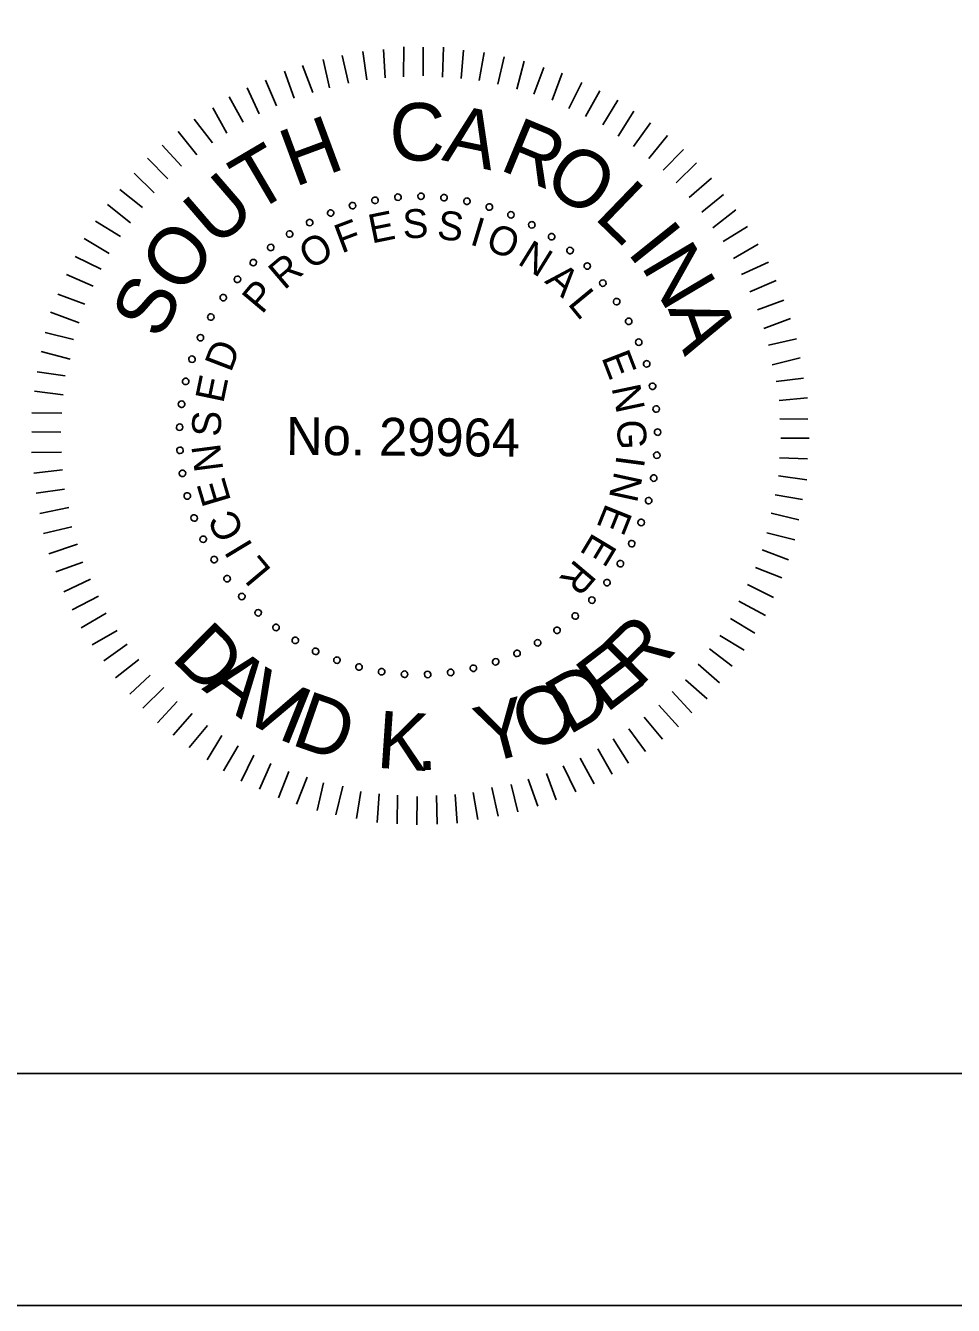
# Model space of a CAD drawing. Extents: x -133.1 to -97, y -1.7 to 20.3.
# Drawn here: x -109.682 to -107.68, y -1.691 to 1.069 of the extents above; entities that cross this region are included whole.
import ezdxf

# ---------------------------------------------------------------- set-up
doc = ezdxf.new("R2010")
doc.units = 0
for name, color, linetype in [('BR_BORDER LINES', 7, 'Continuous'), ('BR_TEXT', 7, 'Continuous'), ('Level 31', 7, 'Continuous')]:
    doc.layers.add(name, color=color, linetype=linetype)

msp = doc.modelspace()

# ---------------------------------------------------------------- linework, layer by layer
at = {"layer": 'BR_BORDER LINES'}
msp.add_line((-131.3076, -1.191), (-97.6416, -1.191), dxfattribs=at)
at = {"layer": 'BR_TEXT'}
for p, q in [((-108.8664, 0.9584), (-108.8658, 1.0227)), ((-108.8243, 0.9606), (-108.8238, 1.0224)), ((-108.7823, 0.9577), (-108.78, 1.022)), ((-109.0262, 0.9348), (-109.0394, 0.9958)), ((-108.9849, 0.9447), (-108.999, 1.0041)), ((-108.9454, 0.9521), (-108.9543, 1.0131)), ((-108.9059, 0.9561), (-108.9097, 1.017)), ((-108.742, 0.9548), (-108.7372, 1.0156)), ((-108.7034, 0.9501), (-108.6926, 1.011)), ((-108.6631, 0.9421), (-108.6489, 1.0012)), ((-109.1019, 0.9122), (-109.1229, 0.9708)), ((-109.0623, 0.9248), (-109.0842, 0.9824)), ((-108.622, 0.9314), (-108.606, 0.9922)), ((-108.5852, 0.9208), (-108.5633, 0.9781)), ((-109.1406, 0.8954), (-109.1642, 0.9514)), ((-108.5458, 0.9076), (-108.5239, 0.9658)), ((-108.5099, 0.8902), (-108.482, 0.9457)), ((-109.2122, 0.8608), (-109.2426, 0.9151)), ((-109.1777, 0.8785), (-109.2039, 0.9345)), ((-108.474, 0.8727), (-108.4427, 0.9282)), ((-109.2475, 0.8371), (-109.278, 0.8914)), ((-108.4364, 0.8544), (-108.4042, 0.9082)), ((-108.4031, 0.8301), (-108.3692, 0.8839)), ((-109.2786, 0.8159), (-109.3177, 0.8668)), ((-108.3699, 0.8083), (-108.3334, 0.8587)), ((-109.3123, 0.7904), (-109.3522, 0.8405)), ((-108.3375, 0.7824), (-108.2968, 0.8318)), ((-109.3451, 0.7658), (-109.3868, 0.8107)), ((-108.3059, 0.7572), (-108.2627, 0.8014)), ((-109.3745, 0.7386), (-109.4188, 0.7827)), ((-108.2779, 0.7295), (-108.2346, 0.7729)), ((-109.4039, 0.7079), (-109.4474, 0.7503)), ((-108.2498, 0.6984), (-108.2022, 0.74)), ((-109.4291, 0.6763), (-109.4786, 0.7154)), ((-108.2226, 0.6664), (-108.1759, 0.7046)), ((-109.4551, 0.6431), (-109.5046, 0.683)), ((-108.1988, 0.6327), (-108.1496, 0.6718)), ((-109.4768, 0.6141), (-109.5306, 0.6472)), ((-108.1768, 0.6034), (-108.1242, 0.6355)), ((-109.5012, 0.5774), (-109.5549, 0.6096)), ((-108.1548, 0.5663), (-108.1013, 0.5976)), ((-109.5186, 0.5432), (-109.575, 0.5711)), ((-108.137, 0.5318), (-108.0793, 0.5588)), ((-109.5361, 0.5065), (-109.5933, 0.5318)), ((-108.1193, 0.4948), (-108.0624, 0.5192)), ((-109.5536, 0.468), (-109.6117, 0.4899)), ((-108.1025, 0.456), (-108.0456, 0.477)), ((-109.5659, 0.4278), (-109.6275, 0.4506)), ((-108.0891, 0.4156), (-108.0314, 0.4374)), ((-109.5782, 0.3918), (-109.639, 0.4069)), ((-108.079, 0.3794), (-108.0189, 0.3935)), ((-109.5854, 0.3498), (-109.6479, 0.3658)), ((-108.0708, 0.3373), (-108.0106, 0.3522)), ((-109.596, 0.3138), (-109.6569, 0.3221)), ((-108.0625, 0.3012), (-108.0033, 0.3084)), ((-109.6006, 0.2727), (-109.6624, 0.2801)), ((-108.056, 0.26), (-107.995, 0.2663)), ((-109.6035, 0.2333), (-109.6679, 0.2338)), ((-108.0546, 0.2205), (-107.9945, 0.22)), ((-109.6056, 0.1921), (-109.6682, 0.1926)), ((-108.0524, 0.1793), (-107.9915, 0.1788)), ((-109.6042, 0.1492), (-109.6686, 0.148)), ((-109.602, 0.1105), (-109.6638, 0.1033)), ((-108.0553, 0.1364), (-107.9952, 0.1342)), ((-108.0574, 0.0978), (-107.9965, 0.0896)), ((-109.598, 0.0693), (-109.659, 0.0604)), ((-108.0645, 0.0566), (-108.0054, 0.0467)), ((-109.5881, 0.0297), (-109.6508, 0.0165)), ((-108.0735, 0.0172), (-108.0135, 0.003)), ((-109.5815, -0.0124), (-109.6426, -0.0265)), ((-108.0824, -0.0248), (-108.0224, -0.0398)), ((-109.5698, -0.0493), (-109.6318, -0.0703)), ((-108.093, -0.0615), (-108.0357, -0.0835)), ((-109.5582, -0.0881), (-109.6167, -0.1091)), ((-108.107, -0.1001), (-108.0506, -0.122)), ((-109.5413, -0.1251), (-109.599, -0.1521)), ((-108.1245, -0.1368), (-108.0681, -0.1647)), ((-109.5244, -0.1613), (-109.5813, -0.1909)), ((-108.1428, -0.1727), (-108.0856, -0.2032)), ((-109.5076, -0.1984), (-109.5619, -0.2297)), ((-108.1612, -0.2095), (-108.1082, -0.2417)), ((-109.4838, -0.2355), (-109.5382, -0.2668)), ((-108.1838, -0.2462), (-108.1317, -0.2784)), ((-109.4626, -0.2648), (-109.5127, -0.3013)), ((-108.2063, -0.2752), (-108.1577, -0.3125)), ((-109.4372, -0.2985), (-109.4873, -0.3376)), ((-108.2306, -0.3084), (-108.1846, -0.3483)), ((-109.4125, -0.3321), (-109.4567, -0.373)), ((-109.3836, -0.3582), (-109.4286, -0.4032)), ((-108.2583, -0.3417), (-108.2115, -0.3833)), ((-108.2869, -0.3672), (-108.2444, -0.413)), ((-109.3547, -0.3884), (-109.3971, -0.4344)), ((-108.3155, -0.397), (-108.273, -0.4437)), ((-109.3222, -0.4144), (-109.363, -0.4613)), ((-109.289, -0.4404), (-109.3289, -0.4882)), ((-108.3474, -0.4225), (-108.3075, -0.47)), ((-109.2583, -0.4622), (-109.2896, -0.5142)), ((-108.4139, -0.4691), (-108.3808, -0.5217)), ((-108.3802, -0.448), (-108.3446, -0.4963)), ((-109.2233, -0.4847), (-109.2546, -0.5386)), ((-108.4475, -0.4911), (-108.4162, -0.5455)), ((-109.1891, -0.5048), (-109.2162, -0.5603)), ((-109.1523, -0.5222), (-109.1769, -0.5778)), ((-108.4855, -0.5106), (-108.455, -0.5666)), ((-109.1139, -0.5397), (-109.1358, -0.5962)), ((-108.5578, -0.5443), (-108.5368, -0.6011)), ((-108.5216, -0.5274), (-108.4947, -0.5835)), ((-109.0745, -0.552), (-109.0973, -0.6102)), ((-109.0386, -0.5644), (-109.0528, -0.6235)), ((-108.9974, -0.5716), (-109.0126, -0.6333)), ((-108.6756, -0.5742), (-108.6624, -0.6361)), ((-108.6344, -0.5677), (-108.6194, -0.627)), ((-108.5974, -0.556), (-108.5764, -0.6145)), ((-108.9581, -0.5831), (-108.968, -0.6413)), ((-108.9186, -0.5877), (-108.9234, -0.6494)), ((-108.8792, -0.5906), (-108.8797, -0.6524)), ((-108.8372, -0.5935), (-108.8377, -0.6544)), ((-108.7951, -0.5913), (-108.7939, -0.6531)), ((-108.7547, -0.589), (-108.7509, -0.6509)), ((-108.7161, -0.5851), (-108.7062, -0.6435))]:
    msp.add_line(p, q, dxfattribs=at)
for centre, start, end in [((-108.9278, 0.692), 10.6038, 190.6038), ((-108.9278, 0.692), 190.6038, 10.6038), ((-108.8784, 0.6987), 5.0653, 185.0653), ((-108.8784, 0.6987), 185.0653, 5.0653), ((-108.8286, 0.7006), 359.5268, 179.5268), ((-108.8286, 0.7006), 179.5268, 359.5268), ((-108.7789, 0.6977), 173.9884, 353.9884), ((-108.7789, 0.6977), 353.9884, 173.9884), ((-108.7296, 0.69), 168.4499, 348.4499), ((-108.7296, 0.69), 348.4499, 168.4499), ((-109.0235, 0.6646), 21.6807, 201.6807), ((-109.0235, 0.6646), 201.6807, 21.6807), ((-108.9763, 0.6806), 16.1422, 196.1422), ((-108.9763, 0.6806), 196.1422, 16.1422), ((-108.6814, 0.6776), 162.9114, 342.9114), ((-108.6814, 0.6776), 342.9114, 162.9114), ((-108.6345, 0.6606), 157.373, 337.373), ((-108.6345, 0.6606), 337.373, 157.373), ((-109.0689, 0.644), 27.2191, 207.2191), ((-109.0689, 0.644), 207.2191, 27.2191), ((-108.5896, 0.6391), 151.8345, 331.8345), ((-108.5896, 0.6391), 331.8345, 151.8345), ((-109.1121, 0.6192), 32.7576, 212.7576), ((-109.1121, 0.6192), 212.7576, 32.7576), ((-108.5469, 0.6134), 146.2961, 326.2961), ((-108.5469, 0.6134), 326.2961, 146.2961), ((-109.1527, 0.5903), 38.2961, 218.2961), ((-109.1527, 0.5903), 218.2961, 38.2961), ((-108.5069, 0.5837), 140.7576, 320.7576), ((-108.5069, 0.5837), 320.7576, 140.7576), ((-109.1903, 0.5577), 43.8345, 223.8345), ((-109.1903, 0.5577), 223.8345, 43.8345), ((-108.4699, 0.5503), 135.2191, 315.2191), ((-108.4699, 0.5503), 315.2191, 135.2191), ((-109.2246, 0.5215), 49.373, 229.373), ((-109.2246, 0.5215), 229.373, 49.373), ((-108.4363, 0.5134), 129.6807, 309.6807), ((-108.4363, 0.5134), 309.6807, 129.6807), ((-109.2553, 0.4822), 54.9114, 234.9114), ((-109.2553, 0.4822), 234.9114, 54.9114), ((-108.4065, 0.4735), 124.1422, 304.1422), ((-108.4065, 0.4735), 304.1422, 124.1422), ((-109.282, 0.4402), 60.4499, 240.4499), ((-109.282, 0.4402), 240.4499, 60.4499), ((-108.3806, 0.4309), 118.6038, 298.6038), ((-108.3806, 0.4309), 298.6038, 118.6038), ((-109.3045, 0.3957), 65.9884, 245.9884), ((-109.3045, 0.3957), 245.9884, 65.9884), ((-108.359, 0.3861), 113.0653, 293.0653), ((-108.359, 0.3861), 293.0653, 113.0653), ((-109.3227, 0.3493), 71.5268, 251.5268), ((-109.3227, 0.3493), 251.5268, 71.5268), ((-108.3418, 0.3393), 107.5268, 287.5268), ((-108.3418, 0.3393), 287.5268, 107.5268), ((-109.3363, 0.3014), 77.0653, 257.0653), ((-109.3363, 0.3014), 257.0653, 77.0653), ((-108.3292, 0.2911), 101.9884, 281.9884), ((-108.3292, 0.2911), 281.9884, 101.9884), ((-109.3452, 0.2524), 82.6038, 262.6038), ((-109.3452, 0.2524), 262.6038, 82.6038), ((-108.3213, 0.2419), 96.4499, 276.4499), ((-108.3213, 0.2419), 276.4499, 96.4499), ((-109.3493, 0.2027), 88.1422, 268.1422), ((-109.3493, 0.2027), 268.1422, 88.1422), ((-108.3182, 0.1921), 90.9114, 270.9114), ((-108.3182, 0.1921), 270.9114, 90.9114), ((-109.3486, 0.1529), 93.6807, 273.6807), ((-109.3486, 0.1529), 273.6807, 93.6807), ((-108.3199, 0.1423), 85.373, 265.373), ((-108.3199, 0.1423), 265.373, 85.373), ((-109.3431, 0.1033), 99.2191, 279.2191), ((-109.3431, 0.1033), 279.2191, 99.2191), ((-108.3265, 0.0929), 79.8345, 259.8345), ((-108.3265, 0.0929), 259.8345, 79.8345), ((-109.3328, 0.0546), 104.7576, 284.7576), ((-109.3328, 0.0546), 284.7576, 104.7576), ((-108.3377, 0.0444), 74.2961, 254.2961), ((-108.3377, 0.0444), 254.2961, 74.2961), ((-109.3179, 0.007), 110.2961, 290.2961), ((-109.3179, 0.007), 290.2961, 110.2961), ((-108.3536, -0.0028), 68.7576, 248.7576), ((-108.3536, -0.0028), 248.7576, 68.7576), ((-109.2985, -0.0389), 115.8345, 295.8345), ((-109.2985, -0.0389), 295.8345, 115.8345), ((-108.374, -0.0483), 63.2191, 243.2191), ((-108.374, -0.0483), 243.2191, 63.2191), ((-109.2747, -0.0826), 121.373, 301.373), ((-109.2747, -0.0826), 301.373, 121.373), ((-108.3986, -0.0916), 57.6807, 237.6807), ((-108.3986, -0.0916), 237.6807, 57.6807), ((-109.2468, -0.1239), 126.9114, 306.9114), ((-109.2468, -0.1239), 306.9114, 126.9114), ((-108.4273, -0.1323), 52.1422, 232.1422), ((-108.4273, -0.1323), 232.1422, 52.1422), ((-109.2151, -0.1624), 132.4499, 312.4499), ((-109.2151, -0.1624), 312.4499, 132.4499), ((-108.4599, -0.1701), 46.6038, 226.6038), ((-108.4599, -0.1701), 226.6038, 46.6038), ((-109.1798, -0.1975), 137.9884, 317.9884), ((-109.1798, -0.1975), 317.9884, 137.9884), ((-108.4959, -0.2045), 41.0653, 221.0653), ((-108.4959, -0.2045), 221.0653, 41.0653), ((-109.1413, -0.2291), 143.5268, 323.5268), ((-109.1413, -0.2291), 323.5268, 143.5268), ((-108.5351, -0.2353), 35.5268, 215.5268), ((-108.5351, -0.2353), 215.5268, 35.5268), ((-109.0999, -0.2569), 149.0653, 329.0653), ((-109.0999, -0.2569), 329.0653, 149.0653), ((-109.056, -0.2805), 334.6038, 154.6038), ((-108.577, -0.2622), 29.9884, 209.9884), ((-108.577, -0.2622), 209.9884, 29.9884), ((-109.056, -0.2805), 154.6038, 334.6038), ((-109.01, -0.2997), 160.1422, 340.1422), ((-109.01, -0.2997), 340.1422, 160.1422), ((-108.6677, -0.3032), 18.9114, 198.9114), ((-108.6677, -0.3032), 198.9114, 18.9114), ((-108.6214, -0.2849), 24.4499, 204.4499), ((-108.6214, -0.2849), 204.4499, 24.4499), ((-108.9624, -0.3145), 165.6807, 345.6807), ((-108.9624, -0.3145), 345.6807, 165.6807), ((-108.9136, -0.3245), 171.2191, 351.2191), ((-108.9136, -0.3245), 351.2191, 171.2191), ((-108.8641, -0.3299), 356.7576, 176.7576), ((-108.8641, -0.3299), 176.7576, 356.7576), ((-108.8142, -0.3304), 2.2961, 182.2961), ((-108.8142, -0.3304), 182.2961, 2.2961), ((-108.7646, -0.3261), 7.8345, 187.8345), ((-108.7646, -0.3261), 187.8345, 7.8345), ((-108.7156, -0.317), 13.373, 193.373), ((-108.7156, -0.317), 193.373, 13.373)]:
    msp.add_arc(centre, 0.00701, start, end, dxfattribs=at)
at = {"layer": 'Level 31'}
msp.add_lwpolyline([(-133.1409, -1.691), (-97.141, -1.691), (-97.141, 20.309), (-133.1409, 20.309)], close=True, dxfattribs=at)

# ---------------------------------------------------------------- texts
at = {"layer": 'BR_TEXT'}
for s, height, rotation, p in [('C', 0.1241, 359.5482, (-108.8971, 0.7782)), ('A', 0.1241, 348.1981, (-108.7857, 0.779)), ('H', 0.1241, 20.3637, (-109.1015, 0.7199)), ('R', 0.1241, 337.4344, (-108.6624, 0.7591)), ('T', 0.1241, 30.4992, (-109.1894, 0.6624)), ('O', 0.1239, 326.5869, (-108.5702, 0.7224)), ('U', 0.1241, 40.8022, (-109.2706, 0.5876)), ('L', 0.1241, 315.9488, (-108.4576, 0.6546)), ('E', 0.0622, 11.4103, (-108.9351, 0.5987)), ('S', 0.0622, 2.208, (-108.8672, 0.6097)), ('S', 0.0622, 352.6608, (-108.796, 0.6095)), ('O', 0.1241, 52.0267, (-109.3451, 0.4837)), ('F', 0.0622, 20.6127, (-109.0002, 0.577)), ('I', 0.0622, 343.1136, (-108.7257, 0.5975)), ('O', 0.0622, 338.4392, (-108.6923, 0.5873)), ('I', 0.1241, 308.6613, (-108.3862, 0.5803)), ('O', 0.0622, 30.8477, (-109.0676, 0.541)), ('N', 0.0622, 328.2042, (-108.6227, 0.5559)), ('N', 0.1241, 300.7037, (-108.3556, 0.5509)), ('R', 0.0622, 40.3949, (-109.1237, 0.4971)), ('S', 0.1239, 63.2511, (-109.3905, 0.3881)), ('A', 0.0622, 318.657, (-108.5637, 0.5159)), ('P', 0.0622, 49.9421, (-109.1718, 0.4445)), ('L', 0.0622, 309.4546, (-108.5139, 0.4686)), ('A', 0.1241, 289.4792, (-108.2964, 0.4579)), ('D', 0.0622, 69.0364, (-109.2388, 0.3192)), ('E', 0.0622, 291.049, (-108.44, 0.3533)), ('E', 0.0622, 78.2388, (-109.2553, 0.2526)), ('N', 0.0622, 281.8466, (-108.4179, 0.2882)), ('S', 0.0622, 87.786, (-109.2611, 0.1815)), ('No. 29964', 0.08175, 359.5268, (-109.1199, 0.1431)), ('G', 0.0622, 272.2995, (-108.4061, 0.2179)), ('N', 0.0622, 97.3332, (-109.2549, 0.1105)), ('I', 0.0622, 262.4084, (-108.4065, 0.1441)), ('E', 0.0622, 106.5355, (-109.2379, 0.044)), ('N', 0.0622, 257.7339, (-108.411, 0.1095)), ('E', 0.0622, 248.1867, (-108.4291, 0.0406)), ('C', 0.0622, 116.4266, (-109.208, -0.0235)), ('I', 0.0622, 121.1011, (-109.1899, -0.0534)), ('E', 0.0622, 238.9844, (-108.457, -0.0222)), ('L', 0.0622, 129.9595, (-109.1493, -0.1056)), ('R', 0.0622, 229.782, (-108.4947, -0.0797)), ('D', 0.1236, 315.4053, (-109.3698, -0.2962)), ('R', 0.1236, 44.5947, (-108.3589, -0.3617)), ('E', 0.1236, 37.5339, (-108.4295, -0.4156)), ('A', 0.1236, 322.8377, (-109.3032, -0.3618)), ('V', 0.1236, 330.5179, (-109.226, -0.42)), ('D', 0.1236, 30.1015, (-108.5104, -0.4626)), ('I', 0.1236, 338.1981, (-109.1418, -0.4674)), ('O', 0.1236, 22.4212, (-108.5997, -0.4996)), ('D', 0.1236, 340.7995, (-109.1119, -0.4808)), ('Y', 0.1236, 14.8649, (-108.6915, -0.5241)), ('K', 0.1236, 356.098, (-108.9267, -0.5314)), ('.', 0.1236, 3.1588, (-108.838, -0.5377))]:
    msp.add_text(s, height=height, rotation=rotation, dxfattribs=at).set_placement(p)

doc.saveas('drawing.dxf')
